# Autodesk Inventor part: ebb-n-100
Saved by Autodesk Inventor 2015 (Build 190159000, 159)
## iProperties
Created: 2020-07
Part Number: ebb-n-100
Checked By: TraceParts S.A.
Material: Generic
Catalog Web Link: www.traceparts.com
Document SubType Name: Modeling
Designer: TraceParts
Density: 1 g/cm^3
Appearance: Default
Company: TraceParts S.A.
Author: TraceParts
REFERENCE: EBB-N-100
DESIGN: EBB-N-100
SUPPLIER: Soler & Palau
TraceParts.PartNumber: 10-04022019-080771
TraceParts.PartTitle: EBB-N
TraceParts.InstanceId: 10-04022019-0807716PE1WMKPED1LCZ3H8F68AGQI9
TraceParts.PartStatus: Published
TraceParts.PartVersion: 1.0.1
TRACEPARTS: TRACEPARTS
TraceParts.PartLanguage: en
TraceParts.ClassPath: SOLER_PALAU:10-04022019-080771
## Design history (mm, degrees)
feature "ebb-n-100"
body "Solid1"
